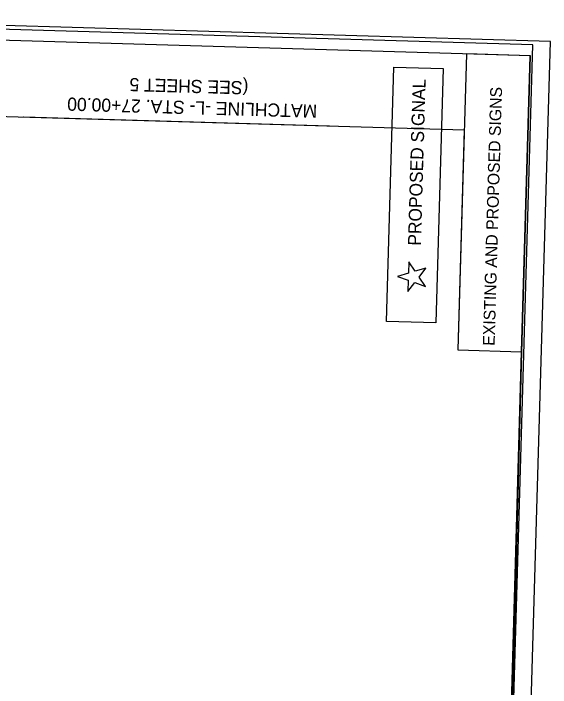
# Model space of a CAD drawing. Extents: x 2096999 to 2102576, y 682920 to 687015.
# Drawn here: x 2097529 to 2098143, y 686071 to 686841 of the extents above; entities that cross this region are included whole.
import ezdxf

# ---------------------------------------------------------------- set-up
doc = ezdxf.new("R2010")
doc.units = 0
for name, color, linetype in [('Default', 7, 'Continuous'), ('Matchline', 7, 'Continuous'), ('Matchline Text', 7, 'Continuous'), ('Old_Level_10', 7, 'Continuous'), ('Scratch_Level_0', 7, 'Continuous'), ('Scratch_Level_2', 7, 'Continuous'), ('Sheet Plan CELL', 7, 'Continuous'), ('Sheet Plot Border Inside CELL', 7, 'Continuous'), ('Sheet Plot Border Outside CELL', 7, 'Continuous')]:
    doc.layers.add(name, color=color, linetype=linetype)

msp = doc.modelspace()

# ---------------------------------------------------------------- linework, layer by layer
at = {"layer": 'Default'}
msp.add_lwpolyline([(2097955.43, 686488.97), (2097963.88, 686779.73), (2098020.4, 686778.09), (2098011.94, 686487.32)], close=True, dxfattribs=at)
msp.add_lwpolyline([(2097980.38, 686536.08), (2097980.01, 686523.17), (2097987.9, 686533.4), (2098000.09, 686529.04), (2097992.79, 686539.74), (2098000.69, 686549.98), (2097988.28, 686546.34), (2097980.98, 686557.01), (2097980.61, 686544.09), (2097968.19, 686540.44), (2097980.38, 686536.08)], dxfattribs=at)
at = {"layer": 'Matchline'}
for p, q in [((2097540.47, 686722.78), (2097890.32, 686712.55)), ((2097540.7, 686722.95), (2097890.55, 686712.78))]:
    msp.add_line(p, q, dxfattribs=at)
at = {"layer": 'Old_Level_10'}
msp.add_lwpolyline([(2098110.03, 686454.34), (2098119.92, 686792.68), (2098047.12, 686794.81), (2098037.23, 686456.47)], close=True, dxfattribs=at)
msp.add_lwpolyline([(2098110.03, 686454.34), (2098119.92, 686792.68), (2098047.12, 686794.81), (2098037.23, 686456.47)], close=True, dxfattribs=at)
at = {"layer": 'Scratch_Level_0'}
msp.add_line((2098076.32, 685293.3), (2098110.07, 686454.34), dxfattribs=at)
at = {"layer": 'Scratch_Level_2'}
msp.add_lwpolyline([(2097234.32, 685317.78), (2097026.76, 685323.81), (2097058.72, 686423.24), (2097059.31, 686437.01), (2097065.14, 686636.69), (2097214.22, 686632.33), (2097231.8, 686631.82), (2097295.87, 686629.95), (2097298.79, 686729.78), (2098044.58, 686708.09), (2098037.23, 686456.47), (2098110.07, 686454.34), (2098090.85, 685704.42)], close=True, dxfattribs=at)
at = {"layer": 'Sheet Plan CELL'}
msp.add_lwpolyline([(2097070.6, 686823.38), (2097026.77, 685323.98), (2098076.32, 685293.3), (2098120.15, 686792.67)], close=True, dxfattribs=at)
msp.add_lwpolyline([(2097070.6, 686823.38), (2097026.77, 685323.98), (2098076.32, 685293.3), (2098120.15, 686792.67)], close=True, dxfattribs=at)
at = {"layer": 'Sheet Plot Border Inside CELL'}
msp.add_lwpolyline([(2098074.34, 685139.8), (2098123.02, 686805.08), (2097068.48, 686835.92), (2097019.79, 685170.63)], close=True, dxfattribs=at)
msp.add_lwpolyline([(2098074.34, 685139.8), (2098123.02, 686805.08), (2097068.48, 686835.92), (2097019.79, 685170.63)], close=True, dxfattribs=at)
at = {"layer": 'Sheet Plot Border Outside CELL'}
msp.add_lwpolyline([(2098093.96, 685126.22), (2098143.15, 686809.01), (2097048.62, 686841), (2096999.42, 685158.22)], close=True, dxfattribs=at)
msp.add_lwpolyline([(2098093.96, 685126.22), (2098143.15, 686809.01), (2097048.62, 686841), (2096999.42, 685158.22)], close=True, dxfattribs=at)

# ---------------------------------------------------------------- texts
at = {"layer": 'Default'}
for s, height, rotation, p in [('PROPOSED SIGNAL', 14.8414, 88.33483, (2097994.9, 686575.42)), ('EXISTING AND PROPOSED SIGNS', 13.5, 88.3254, (2098079.19, 686461.05))]:
    msp.add_text(s, height=height, rotation=rotation, dxfattribs=at).set_placement(p)
at = {"layer": 'Matchline Text'}
for s, p in [('(SEE SHEET 5', (2097797.87, 686763.37)), ('MATCHLINE -L- STA. 27+00.00', (2097876.55, 686736.7))]:
    msp.add_text(s, height=15, rotation=178.33483, dxfattribs=at).set_placement(p)

doc.saveas('drawing.dxf')
